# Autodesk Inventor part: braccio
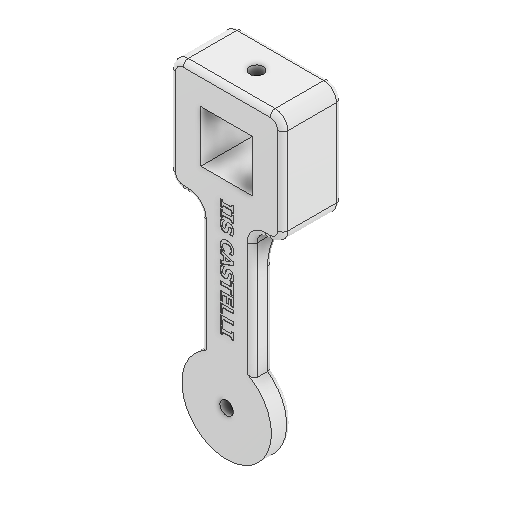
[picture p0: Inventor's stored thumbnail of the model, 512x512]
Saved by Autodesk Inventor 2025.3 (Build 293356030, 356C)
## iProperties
Created: 2025-09
Part Number: braccio
Material: Plastica ABS
Document SubType Name: Modeling
Designer: Ryzen5700u
Density: 1.06 g/cm^3
Appearance: Liscia - Bianco
Author: Ryzen5700u
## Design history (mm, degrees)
sketch "Schizzo1"
  geometry: L1 (-10.1, -10.1)-(10.1, -10.1); L2 (10.1, -10.1)-(10.1, 10.1); L3 (10.1, 10.1)-(-10.1, 10.1); L4 (-10.1, 10.1)-(-10.1, -10.1); L5 (-10.1, -10.1)-(10.1, 10.1); L6 (10.1, -10.1)-(-10.1, 10.1); L7 (-22, -22)-(22, -22); L8 (22, -22)-(22, 22); L9 (22, 22)-(-22, 22); L10 (-22, 22)-(-22, -22); L11 (-22, -22)-(22, 22); L12 (22, -22)-(-22, 22); L13 (-10, -22)-(10, -22); L14 (10, -22)-(10, -97); L15 (10, -97)-(-10, -97); L16 (-10, -97)-(-10, -22); 2 further points
  constraints: 32 end point, 6 parallel, 4 midpoint, 3 horizontal, 3 perpendicular, 1 point on line
  dimensions: "d0" = 20.2 distance of L3.end L2.end; "d1" = 20.2 distance of L2.end L1.end; "d2" = 44 distance of L9.end L8.end; "d3" = 44 distance of L7.end L8.end; "d4" = 75 distance of L13.end L14.end
extrude "Estrusione1" new body sketch "Schizzo1" distance "d5" = 8; taper "d6" = 0 deg
sketch "Schizzo2"
  geometry: L1 (22, -22)-(10, -22) reference; L2 (22, 22)-(22, -22) reference; L3 (-22, 22)-(22, 22) reference; L4 (-22, -22)-(-22, 22) reference; L5 (-10, -22)-(-22, -22) reference; L6 (-10, -97)-(-10, -22) reference; L7 (10, -97)-(-10, -97) reference; L8 (10, -22)-(10, -97) reference; L9 (10.1, -10.1)-(10.1, 10.1) reference; L10 (-10.1, -10.1)-(10.1, -10.1) reference; L11 (-10.1, 10.1)-(-10.1, -10.1) reference; L12 (10.1, 10.1)-(-10.1, 10.1) reference; L13 (10, -22)-(-10, -22); 1 further point
  constraints: 2 end point, 1 horizontal
extrude "Estrusione2" join sketch "Schizzo2" distance "d7" = 15; taper "d8" = 0 deg
sketch "Schizzo3"
  geometry: L1 (44, 23)-(44, 0) reference; L2 (44, 23)-(0, 23) reference; L3 (44, 0)-(0, 23); L4 (0, 0)-(0, 23) reference; L5 (0, 23)-(0, 0); L6 (0, 0)-(45.029, 22.647); 2 further points
  constraints: 6 end point, 2 point on line, 1 collinear
hole "Foro1" sketch "Schizzo3" at (22.424, 11.278) diameter "d9" = 5.3; stored, may be unused: countersink angle "d13" = 90 deg, drill point angle "d15" = 118 deg; dims "d10" = 6, "d11" = 10, "d12" = 5.7, "d14" = 64.25
fillet "Raccordo1" dims "d16" = 5
sketch "Schizzo6"
  geometry: L1 (2.697, -16.966)-(2.697, -70.179); L2 (2.697, -70.179)-(-3.392, -70.179); L3 (-3.392, -70.179)-(-3.392, -16.966); L4 (-3.392, -16.966)-(2.697, -16.966); 1 further point
  constraints: 2 other
extrude "Estrusione5" cut sketch "Schizzo6" distance "d23" = 0.2; taper "d24" = 0 deg
fillet "Raccordo3" dims "d25" = 15
fillet "Raccordo6" dims "d28" = 10
sketch "Schizzo7"
  geometry: L1 (10, -87)-(10, -27) reference; L2 (15, -22)-(17, -22) reference; L3 (22, -17)-(22, 17) reference; L4 (17, 22)-(-17, 22) reference; L5 (-22, 17)-(-22, -17) reference; L6 (-17, -22)-(-15, -22) reference; L7 (-10, -27)-(-10, -87) reference; L8 (-1.448, -59.863)-(-2.4, -59.863) reference; L9 (-2.4, -59.863)-(-2.4, -56.528) reference; L10 (-2.4, -56.528)-(2.6, -56.528) reference; L11 (2.6, -56.528)-(2.6, -57.784) reference; L12 (2.6, -57.784)-(-1.448, -57.784) reference; L13 (-1.448, -57.784)-(-1.448, -59.863) reference; L14 (-2.4, -51.743)-(-2.4, -48.364) reference; L15 (-2.4, -48.364)-(2.6, -48.364) reference; L16 (2.6, -48.364)-(2.6, -51.743) reference; L17 (2.6, -51.743)-(1.647, -51.743) reference; L18 (1.647, -51.743)-(1.647, -49.612) reference; L19 (1.647, -49.612)-(0.768, -49.612) reference; L20 (0.768, -49.612)-(0.768, -51.577) reference; L21 (0.768, -51.577)-(-0.184, -51.577) reference; L22 (-0.184, -51.577)-(-0.184, -49.612) reference; L23 (-0.184, -49.612)-(-1.448, -49.612) reference; L24 (-1.448, -49.612)-(-1.448, -51.743) reference; L25 (-1.448, -51.743)-(-2.4, -51.743) reference; L26 (-2.105, -39.527)-(-0.913, -39.527) reference; L27 (-0.913, -39.527)-(-0.913, -39.64) reference; L28 (2.352, -43.311)-(1.21, -43.311) reference; L29 (1.21, -43.311)-(1.21, -43.202) reference; L30 (-2.4, -35.807)-(-2.4, -34.551) reference; L31 (-2.4, -34.551)-(2.6, -36.241) reference; L32 (2.6, -36.241)-(2.6, -37.61) reference; L33 (2.6, -37.61)-(-2.4, -39.3) reference; L34 (-2.4, -39.3)-(-2.4, -38.007) reference; L35 (-2.4, -38.007)-(-1.379, -37.695) reference; L36 (-1.379, -37.695)-(-1.379, -36.123) reference; L37 (-1.379, -36.123)-(-2.4, -35.807) reference; L38 (-2.105, -23.858)-(-0.913, -23.858) reference; L39 (-0.913, -23.858)-(-0.913, -23.972) reference; L40 (2.352, -27.643)-(1.21, -27.643) reference; L41 (1.21, -27.643)-(1.21, -27.533) reference; L42 (-1.529, -19.972)-(-2.4, -19.972) reference; L43 (-2.4, -19.972)-(-2.4, -17.282) reference; L44 (-2.4, -17.282)-(-1.529, -17.282) reference; L45 (-1.529, -17.282)-(-1.529, -17.999) reference; L46 (-1.529, -17.999)-(1.728, -17.999) reference; L47 (1.728, -17.999)-(1.728, -17.282) reference; L48 (1.728, -17.282)-(2.6, -17.282) reference; L49 (2.6, -17.282)-(2.6, -19.972) reference; L50 (2.6, -19.972)-(1.728, -19.972) reference; L51 (1.728, -19.972)-(1.728, -19.255) reference; L52 (1.728, -19.255)-(-1.529, -19.255) reference; L53 (-1.529, -19.255)-(-1.529, -19.972) reference; L54 (-1.529, -23.295)-(-2.4, -23.295) reference; L55 (-2.4, -23.295)-(-2.4, -20.604) reference; L56 (-2.4, -20.604)-(-1.529, -20.604) reference; L57 (-1.529, -20.604)-(-1.529, -21.322) reference; L58 (-1.529, -21.322)-(1.728, -21.322) reference; L59 (1.728, -21.322)-(1.728, -20.604) reference; L60 (1.728, -20.604)-(2.6, -20.604) reference; L61 (2.6, -20.604)-(2.6, -23.295) reference; L62 (2.6, -23.295)-(1.728, -23.295) reference; L63 (1.728, -23.295)-(1.728, -22.578) reference; L64 (1.728, -22.578)-(-1.529, -22.578) reference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; C1 r 17.5 at (0, -87); A1 r 10 centre (0, -87) between (-10, -87) and (10, -87) reference; A2 r 10 centre (0, -87) between (-10, -87) and (10, -87) reference; A3 r 5 centre (15, -27) between (15, -22) and (10, -27) reference; A4 r 5 centre (17, -17) between (17, -22) and (22, -17) reference; A5 r 5 centre (17, 17) between (22, 17) and (17, 22) reference; A6 r 5 centre (-17, 17) between (-17, 22) and (-22, 17) reference; A7 r 5 centre (-17, -17) between (-22, -17) and (-17, -22) reference; A8 r 5 centre (-15, -27) between (-10, -27) and (-15, -22) reference; 45 further points
  constraints: 1 centre point, 1 coincident, 46 other
  dimensions: "d29" = 35 diameter of C1
extrude "Estrusione6" join sketch "Schizzo7" stored distance "d30" = 10; taper "d31" = 0 deg
sketch "Schizzo8"
  geometry: A1 r 17.5 centre (0, -87) between (-10, -72.639) and (10, -72.639) reference; 1 further point
hole "Foro2" sketch "Schizzo8" at (0, -87) diameter "d32" = 5.3; stored, may be unused: countersink angle "d36" = 90 deg, drill point angle "d38" = 118 deg; dims "d33" = 6, "d34" = 8, "d35" = 4.6, "d37" = 8
sketch "Schizzo9"
  geometry: L1 (5, -87)-(2.5, -91.33); L2 (2.5, -91.33)-(-2.5, -91.33); L3 (-2.5, -91.33)-(-5, -87); L4 (-5, -87)-(-2.5, -82.67); L5 (-2.5, -82.67)-(2.5, -82.67); L6 (2.5, -82.67)-(5, -87); C1 r 2.65 at (0, -87) reference; 2 further points
  constraints: 12 end point, 1 coincident, 13 other
  dimensions: "d39" = 5 distance of L1.end L2.end
extrude "Estrusione7" cut sketch "Schizzo9" distance "d40" = 3.5; taper "d41" = 0 deg
fillet "Raccordo7" dims "d42" = 2
fillet "Raccordo8" dims "d43" = 2
node "Solido1"
node "Linea chiusa proiettata1"
node "Linea chiusa proiettata2"
